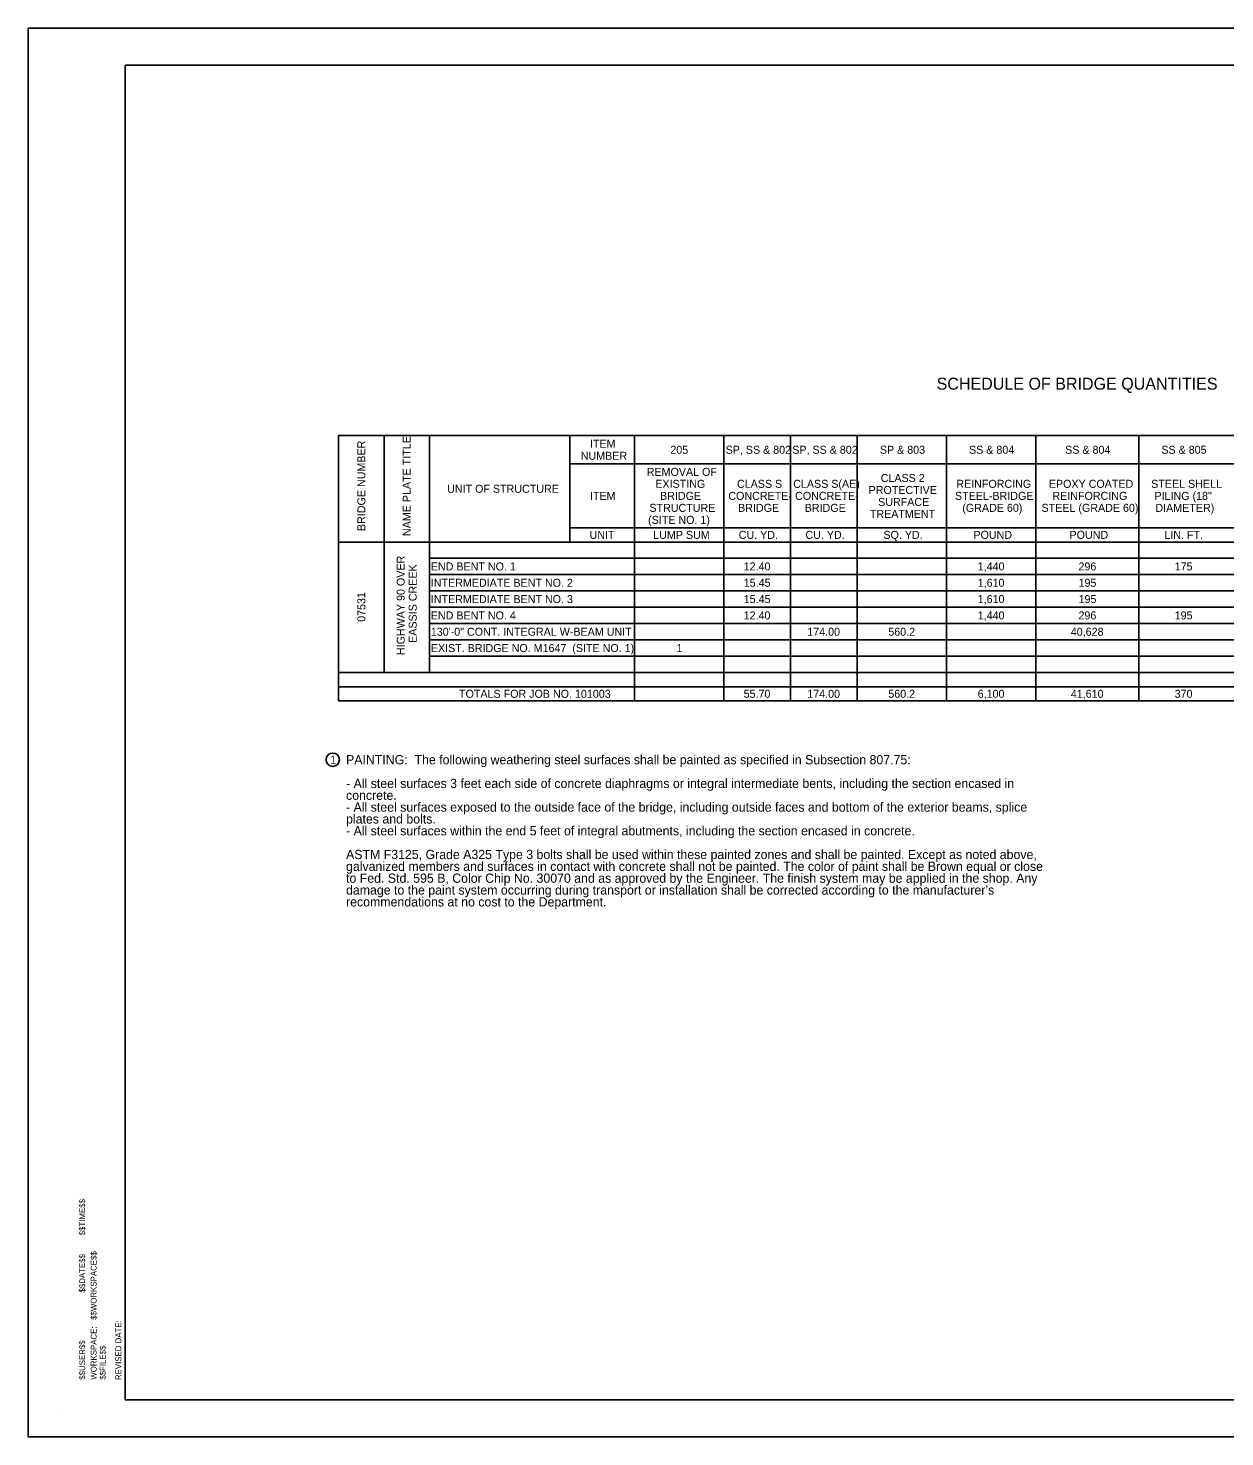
# Model space of a CAD drawing. Extents: x 188 to 14744886, y 129 to 1829278.
# Drawn here: x 187.88 to 206.58, y 128.51 to 150.51 of the extents above; entities that cross this region are included whole.
import ezdxf

# ---------------------------------------------------------------- set-up
doc = ezdxf.new("R2010")
doc.units = 0
for name, color, linetype in [('B_Dimensions', 7, 'Continuous'), ('B_Text', 7, 'Continuous'), ('B_Title Text', 7, 'Continuous'), ('R_Border', 7, 'Continuous')]:
    doc.layers.add(name, color=color, linetype=linetype)

msp = doc.modelspace()

# ---------------------------------------------------------------- linework, layer by layer
at = {"layer": 'B_Dimensions'}
msp.add_line((192.733, 144.151), (192.733, 144.151), dxfattribs=at)
at = {"layer": 'B_Text'}
for p, q in [((192.733, 144.151), (217.973, 144.151)), ((192.733, 140.007), (192.733, 144.151)), ((193.442, 140.451), (193.442, 144.151)), ((194.151, 140.451), (194.151, 144.151)), ((196.345, 142.489), (196.345, 144.151)), ((197.353, 140.007), (197.353, 144.151)), ((198.749, 140.007), (198.749, 144.151)), ((199.791, 140.007), (199.791, 144.151)), ((200.832, 140.007), (200.832, 144.151)), ((202.228, 140.007), (202.228, 144.151)), ((203.624, 140.007), (203.624, 144.151)), ((205.231, 140.007), (205.231, 144.151)), ((196.345, 143.708), (217.973, 143.708)), ((196.345, 142.711), (217.973, 142.711)), ((192.733, 142.489), (217.973, 142.489)), ((194.151, 142.234), (217.973, 142.234)), ((194.151, 141.98), (217.973, 141.98)), ((194.151, 141.725), (217.973, 141.725)), ((194.151, 141.47), (217.973, 141.47)), ((194.151, 141.215), (217.973, 141.215)), ((194.151, 140.96), (217.973, 140.96)), ((194.151, 140.705), (217.973, 140.705)), ((192.733, 140.451), (217.973, 140.451)), ((192.733, 140.229), (217.973, 140.229)), ((192.733, 140.007), (217.973, 140.007))]:
    msp.add_line(p, q, dxfattribs=at)
msp.add_circle((192.641, 139.089), 0.104, dxfattribs=at)
at = {"layer": 'R_Border'}
for p, q in [((189.399, 149.937), (221.306, 149.937)), ((189.399, 129.091), (189.399, 149.937)), ((188.351, 128.942), (188.351, 128.942)), ((221.306, 129.091), (189.399, 129.091))]:
    msp.add_line(p, q, dxfattribs=at)
msp.add_lwpolyline([(187.883, 150.514), (221.883, 150.514), (221.883, 128.514), (187.883, 128.514)], close=True, dxfattribs=at)

# ---------------------------------------------------------------- texts
at = {"layer": 'B_Text'}
for s, height, p in [('SCHEDULE OF BRIDGE QUANTITIES', 0.1875, (202.074, 144.868)), ('NUMBER', 0.125, (196.515, 143.773)), ('ITEM', 0.125, (196.659, 143.961)), ('205', 0.125, (197.915, 143.867)), ('SP, SS & 802', 0.125, (198.778, 143.867)), ('SP, SS & 802', 0.125, (199.819, 143.867)), ('SP & 803', 0.125, (201.188, 143.867)), ('SS & 804', 0.125, (202.58, 143.867)), ('SS & 804', 0.125, (204.082, 143.867)), ('SS & 805', 0.125, (205.585, 143.867)), ('REMOVAL OF', 0.125, (197.546, 143.522)), ('EXISTING', 0.125, (197.68, 143.335)), ('CLASS S', 0.125, (198.956, 143.335)), ('CLASS S(AE)', 0.125, (199.834, 143.335)), ('CLASS 2', 0.1248, (201.201, 143.426)), ('REINFORCING', 0.125, (202.382, 143.335)), ('EPOXY COATED', 0.125, (203.827, 143.335)), ('STEEL SHELL', 0.125, (205.426, 143.335)), ('UNIT OF STRUCTURE', 0.125, (194.428, 143.258)), ('ITEM', 0.125, (196.659, 143.147)), ('BRIDGE', 0.125, (197.754, 143.147)), ('CONCRETE-', 0.125, (198.821, 143.147)), ('CONCRETE-', 0.125, (199.863, 143.147)), ('PROTECTIVE', 0.1248, (201.012, 143.239)), ('STEEL-BRIDGE', 0.125, (202.361, 143.147)), ('REINFORCING', 0.125, (203.883, 143.147)), ('PILING (18"', 0.125, (205.477, 143.147)), ('STRUCTURE', 0.125, (197.587, 142.96)), ('BRIDGE', 0.125, (198.973, 142.96)), ('BRIDGE', 0.125, (200.014, 142.96)), ('SURFACE', 0.1248, (201.161, 143.052)), ('(GRADE 60)', 0.125, (202.476, 142.96)), ('STEEL (GRADE 60)', 0.125, (203.713, 142.96)), ('DIAMETER)', 0.125, (205.492, 142.96)), ('(SITE NO. 1)', 0.125, (197.567, 142.772)), ('TREATMENT', 0.1248, (201.031, 142.865)), ('UNIT', 0.125, (196.653, 142.538)), ('LUMP SUM', 0.125, (197.647, 142.538)), ('CU. YD.', 0.125, (198.983, 142.538)), ('CU. YD.', 0.125, (200.025, 142.538)), ('SQ. YD.', 0.125, (201.243, 142.538)), ('POUND', 0.125, (202.649, 142.538)), ('POUND', 0.125, (204.15, 142.538)), ('LIN. FT.', 0.125, (205.631, 142.538)), ('END BENT NO. 1', 0.125, (194.173, 142.045)), ('12.40', 0.125, (199.06, 142.045)), ('1,440', 0.125, (202.716, 142.045)), ('296', 0.125, (204.29, 142.045)), ('175', 0.125, (205.793, 142.045)), ('INTERMEDIATE BENT NO. 2', 0.125, (194.173, 141.79)), ('15.45', 0.125, (199.061, 141.79)), ('1,610', 0.125, (202.716, 141.79)), ('195', 0.125, (204.291, 141.79)), ('INTERMEDIATE BENT NO. 3', 0.125, (194.173, 141.535)), ('15.45', 0.125, (199.061, 141.535)), ('1,610', 0.125, (202.716, 141.535)), ('195', 0.125, (204.291, 141.535)), ('END BENT NO. 4', 0.125, (194.173, 141.28)), ('12.40', 0.125, (199.06, 141.28)), ('1,440', 0.125, (202.716, 141.28)), ('296', 0.125, (204.29, 141.28)), ('195', 0.125, (205.793, 141.28)), ('130\'-0" CONT. INTEGRAL W-BEAM UNIT', 0.125, (194.173, 141.025)), ('174.00', 0.125, (200.054, 141.025)), ('560.2', 0.125, (201.32, 141.025)), ('40,628', 0.125, (204.17, 141.025)), ('EXIST. BRIDGE NO. M1647  (SITE NO. 1)', 0.125, (194.173, 140.77)), ('1', 0.125, (198.011, 140.77)), ('TOTALS FOR JOB NO. 101003', 0.125, (194.614, 140.056)), ('55.70', 0.125, (199.06, 140.056)), ('174.00', 0.125, (200.054, 140.056)), ('560.2', 0.125, (201.32, 140.056)), ('6,100', 0.125, (202.716, 140.056)), ('41,610', 0.125, (204.171, 140.056)), ('370', 0.125, (205.792, 140.056)), ('1', 0.125, (192.601, 139.026))]:
    msp.add_text(s, height=height, dxfattribs=at).set_placement(p)
for s, p in [('NAME PLATE TITLE', (193.859, 142.582)), ('BRIDGE NUMBER', (193.15, 142.66)), ('HIGHWAY 90 OVER', (193.765, 140.723)), ('EASSIS CREEK', (193.953, 140.914)), ('07531', (193.15, 141.242))]:
    msp.add_text(s, height=0.125, rotation=90, dxfattribs=at).set_placement(p)
at = {"layer": 'B_Title Text'}
for s, p in [('PAINTING:  The following weathering steel surfaces shall be painted as specified in Subsection 807.75:', (192.849, 139.017)), ('- All steel surfaces 3 feet each side of concrete diaphragms or integral intermediate bents, including the section encased in ', (192.849, 138.647)), ('concrete.', (192.849, 138.462)), ('- All steel surfaces exposed to the outside face of the bridge, including outside faces and bottom of the exterior beams, splice ', (192.849, 138.277)), ('plates and bolts.', (192.849, 138.092)), ('- All steel surfaces within the end 5 feet of integral abutments, including the section encased in concrete.', (192.849, 137.907)), ('ASTM F3125, Grade A325 Type 3 bolts shall be used within these painted zones and shall be painted. Except as noted above, ', (192.849, 137.537)), ('galvanized members and surfaces in contact with concrete shall not be painted. The color of paint shall be Brown equal or close ', (192.849, 137.352)), ('to Fed. Std. 595 B, Color Chip No. 30070 and as approved by the Engineer. The finish system may be applied in the shop. Any ', (192.849, 137.167)), ('damage to the paint system occurring during transport or installation shall be corrected according to the manufacturer’s ', (192.849, 136.982)), ('recommendations at no cost to the Department.', (192.849, 136.797))]:
    msp.add_text(s, height=0.144, dxfattribs=at).set_placement(p)
at = {"layer": 'R_Border'}
for s, p in [('$$TIME$$', (188.773, 131.661)), ('$$DATE$$', (188.773, 130.768)), ('$$WORKSPACE$$', (188.952, 130.341)), ('REVISED DATE:', (189.338, 129.4)), ('WORKSPACE:', (188.952, 129.406)), ('$$USER$$', (188.773, 129.406)), ('$$FILE$$', (189.094, 129.406))]:
    msp.add_text(s, height=0.0918, rotation=90, dxfattribs=at).set_placement(p)

doc.saveas('drawing.dxf')
